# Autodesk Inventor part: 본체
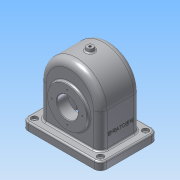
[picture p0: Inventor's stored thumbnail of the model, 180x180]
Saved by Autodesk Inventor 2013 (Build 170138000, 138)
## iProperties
Created: 2016-10
Part Number: 본체
Material: 알루미늄 6061
Document SubType Name: Modeling
Designer: user
Density: 2.71 g/cm^3
Mass: 1140.15 g
Surface Area: 1193.68 cm^2
Volume: 420.719 cm^3
Author: user
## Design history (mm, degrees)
sketch "스케치1"
  geometry: L1 (75, -55)-(-75, -55); L2 (-75, -55)-(-75, 55); L3 (-75, 55)-(75, 55); L4 (75, 55)-(75, -55); L5 (75, -55)-(-75, 55); L6 (-75, -55)-(75, 55); 1 further point
  constraints: 12 end point, 2 midpoint, 2 parallel, 1 horizontal, 1 perpendicular
  dimensions: "d0" = 150 distance of L1.start L1.end; "d2" = 110 distance of L3.end L1.start
extrude "돌출1" new body sketch "스케치1" distance "d3" = 15; taper "d4" = 0 deg
sketch "스케치2"
  geometry: L1 (-75.646, 80)-(75.646, 80); L2 (-75, 0)-(75, 0) reference; L3 (-58, 80)-(-58, 0); L4 (58, 80)-(58, 0); L5 (-58, 0)-(58, 0); A1 r 58 centre (0, 80) between (-58, 80) and (58, 80); 3 further points
  constraints: 8 end point, 4 point on line, 2 midpoint, 2 perpendicular, 2 point on circle, 2 tangent, 1 centre point, 1 coincident, 1 collinear, 1 horizontal, 1 vertical alignment
  dimensions: "d5" = 80 distance between parallel lines of L2 L1; "d6" = 116 diameter of A1
extrude "돌출2" join sketch "스케치2" stored distance "d7" = 77; taper "d8" = 0 deg
sketch "스케치3"
  geometry: L1 (75, 0)-(-75, 0) reference; C1 r 37.5 at (0, 65); 2 further points
  constraints: 1 centre point, 1 midpoint, 1 vertical alignment
  dimensions: "d12" = 75 diameter of C1; "d14" = 65 distance from line of L1 C1.centre
extrude "돌출3" join sketch "스케치3" distance "d15" = 5; taper "d16" = 0 deg
sketch "스케치4"
  geometry: L1 (75, 0)-(-75, 0) reference; C1 r 31 at (0, 65); 2 further points
  constraints: 1 centre point, 1 midpoint, 1 vertical alignment
  dimensions: "d17" = 62 diameter of C1; "d19" = 65 distance from line of L1 C1.centre
extrude "돌출4" join sketch "스케치4" distance "d20" = 10; taper "d21" = 0 deg
sketch "스케치7"
  geometry: L1 (-64.353, 113.349)-(56.669, 113.349); L2 (-6, 144)-(6, 144); L3 (6, 144)-(11.405, 113.349); L4 (-6, 144)-(-11.405, 113.349); L5 (-75, 0)-(75, 0) reference; L6 (0, 144)-(0, 113.349); 1 further point
  constraints: 10 end point, 3 point on line, 1 horizontal, 1 midpoint, 1 parallel, 1 perpendicular, 1 vertical alignment
  dimensions: "d27" = 144 distance between parallel lines of L5 L2; "d28" = 100 deg angle of L4 L1; "d29" = 100 deg angle of L1 L3; "d30" = 113.34911 distance between parallel lines of L5 L1; "d31" = 12 distance of L2.start L2.end
revolve "회전1" sketch "스케치7" stored, may be unused: angle "d32" = 90 deg
sketch "스케치10"
  geometry: L1 (-58, 15)-(58, 15) reference; L2 (-58, 15)-(-58, 80) reference; L3 (58, 80)-(58, 15) reference; L4 (-52, 80)-(-52, 0); L5 (52, 80)-(52, 0); L6 (52, 0)-(-52, 0); C1 r 31 at (0, 65) reference; A1 r 58 centre (0, 80) between (58, 80) and (-58, 80) reference; A2 r 52 centre (0, 80) between (-52, 80) and (52, 80); 1 further point
  constraints: 6 end point, 2 perpendicular, 2 point on circle, 2 tangent, 1 centre point, 1 coincident, 1 parallel
  dimensions: "d40" = 104 diameter of A2
extrude "돌출6" cut sketch "스케치10" stored distance "d43" = 67; taper "d44" = 0 deg
sketch "스케치12"
  geometry: L1 (102.5, 43.5)-(27.5, 43.5) reference; L2 (34, -48.5)-(96, -48.5) reference; L3 (132, -33.5)-(132, 33.5) reference; L4 (138, 38.5)-(80, 38.5) reference; L5 (132, 33.5)-(80, 33.5) reference; L6 (65, 43.5)-(65, -48.5); L7 (65, 22.178)-(93, 22.178); L8 (93, 22.178)-(102.5, 33.5); L9 (102.5, 33.5)-(65, 33.5); 1 further point
  constraints: 8 end point, 3 point on line, 2 midpoint, 2 perpendicular
  dimensions: "d45" = 56 diameter of L7.end L6; "d47" = 50 deg angle of L7 L8; "d49" = 75 diameter of L8.end L6
revolve "회전2" sketch "스케치12" stored, may be unused: angle "d50" = 90 deg
sketch "스케치13"
  geometry: C1 r 37.5 at (0, 0) reference; 1 further point
hole "구멍1" sketch "스케치13" at (0, 0) diameter "d51" = 40; stored, may be unused: countersink angle "d55" = 90 deg, drill point angle "d57" = 118 deg; dims "d52" = 6, "d53" = 4, "d54" = 2, "d56" = 8
fillet "모깎기1" dims "d58" = 8
chamfer "모따기1" distance "d59" = 1; stored, may be unused: second distance "d60" = 2, angle "d61" = 45 deg
fillet "모깎기2" dims "d62" = 3
fillet "모깎기3" dims "d63" = 13
sketch "스케치14" dims "d64" = 58
  geometry: C1 r 21 at (0, 0) reference; 3 further points
  constraints: 1 coincident, 1 vertical alignment, 2 other
hole "구멍2" sketch "스케치14" at (0, 29) diameter "d66" = 2.459; stored, may be unused: countersink angle "d70" = 90 deg, drill point angle "d72" = 118 deg; dims "d67" = 6, "d68" = 4, "d69" = 2, "d71" = 8
sketch "스케치15" dims "d76" = 52
  geometry: C1 r 21 at (0, 0) reference; 3 further points
  constraints: 1 coincident, 1 vertical alignment, 2 other
hole "구멍3" sketch "스케치15" at (0, 26) diameter "d78" = 2.459; stored, may be unused: countersink angle "d82" = 90 deg, drill point angle "d84" = 118 deg; dims "d79" = 6, "d80" = 4, "d81" = 2, "d83" = 8
fillet "모깎기4" dims "d88" = 3
fillet "모깎기5" dims "d89" = 3
fillet "모깎기6" dims "d90" = 12
fillet "모깎기7" dims "d91" = 3
sketch "스케치18"
  geometry: C1 r 6 at (0, 0) reference
hole "구멍4" sketch "스케치18" at (0, 0) diameter "d92" = 4.459; stored, may be unused: countersink angle "d96" = 90 deg, drill point angle "d98" = 118 deg; dims "d93" = 6, "d94" = 4, "d95" = 2, "d97" = 8
sketch "스케치19"
  geometry: A1 r 9 centre (63, -43) between (63, -52) and (72, -43) reference; A2 r 9 centre (63, 43) between (72, 43) and (63, 52) reference; A3 r 9 centre (-63, 43) between (-63, 52) and (-72, 43) reference; A4 r 9 centre (-63, -43) between (-72, -43) and (-63, -52) reference; 1 further point
hole "구멍5" sketch "스케치19" at (-63, 43), (-63, -43), (63, -43), (63, 43) diameter "d99" = 5; stored, may be unused: countersink angle "d103" = 90 deg, drill point angle "d105" = 118 deg; dims "d100" = 6, "d101" = 12, "d102" = 5, "d104" = 8
sketch "스케치20"
  geometry: L1 (-13, 0)-(-13, -62) reference; L2 (68.5, -80)-(-17.5, -80) reference; 2 further points
  constraints: 1 other
  dimensions: "d106" = 40 distance from line of L2 point (25.5, -40); "d107" = 38.5 distance from line of L1 point (25.5, -40)
feature "엠보싱1" sketch "스케치20" dims "d0" = 150, "d2" = 110, "d108" = 0.5, "d109" = 0
node "솔리드1"
pattern_circular "원형 패턴1" dims angle "d74" = 360 deg
pattern_circular "원형 패턴2" dims angle "d86" = 360 deg
node "투영된 루프1"
